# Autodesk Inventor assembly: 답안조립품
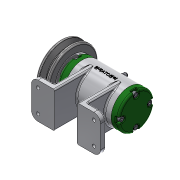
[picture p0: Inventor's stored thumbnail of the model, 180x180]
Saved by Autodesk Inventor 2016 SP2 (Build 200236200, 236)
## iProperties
Created: 2017-02
Part Number: 답안조립품
Material: 일반
Document SubType Name: Assembly
Designer: H
Author: H
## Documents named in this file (16)
- C:\Users\CAMTIC\Desktop\470207V1009\답안조립품.iam
- C:\Users\CAMTIC\Desktop\470207V1009\본체.ipt
- C:\Users\CAMTIC\Desktop\470207V1009\V벨트풀리.ipt
- C:\Users\CAMTIC\Desktop\470207V1009\너트 M 8.ipt
- C:\Users\CAMTIC\Desktop\470207V1009\니플 M 6 x 0.75.ipt
- C:\Users\CAMTIC\Desktop\470207V1009\뒤커버.ipt
- C:\Users\CAMTIC\Desktop\470207V1009\베어링 15 x 32 x 9.ipt
- C:\Users\CAMTIC\Desktop\470207V1009\볼트 M 6 x 8.ipt
- C:\Users\CAMTIC\Desktop\470207V1009\볼트 M4 x 12.ipt
- C:\Users\CAMTIC\Desktop\470207V1009\스프링와셔 8.ipt
- C:\Users\CAMTIC\Desktop\470207V1009\앞커버.ipt
- C:\Users\CAMTIC\Desktop\470207V1009\오일 실 15 25 7.ipt
- C:\Users\CAMTIC\Desktop\470207V1009\와셔 6x11.5.ipt
- C:\Users\CAMTIC\Desktop\470207V1009\와셔 8x17.ipt
- C:\Users\CAMTIC\Desktop\470207V1009\축.ipt
- C:\Users\CAMTIC\Desktop\470207V1009\키 3 x 3 x 12.ipt
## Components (11 placed, 3 different names)
1. V벨트풀리:1
2. KS B 2023 6002 - 15 x 32 x 9:1
3. KS B 2023 6002 - 15 x 32 x 9:2
4. ISO 4762 M4 x 12:2
5. ISO 4762 M4 x 12:3
6. ISO 4762 M4 x 12:4
7. ISO 4762 M4 x 12:5
8. ISO 4762 M4 x 12:1
9. ISO 4762 M4 x 12:6
10. ISO 4762 M4 x 12:7
11. ISO 4762 M4 x 12:8
